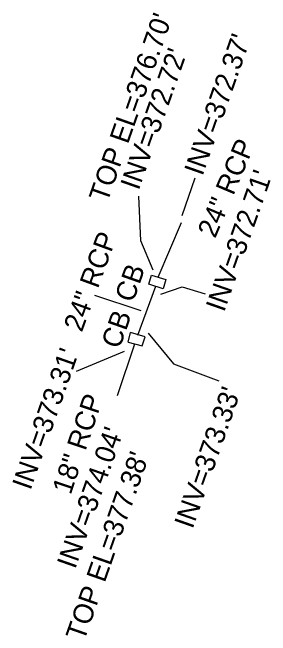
# Model space of a CAD drawing. Extents: x 1975859 to 1978323, y 778892 to 782836.
# Drawn here: x 1977542 to 1977593.8, y 781267.8 to 781393 of the extents above; entities that cross this region are included whole.
import ezdxf

# ---------------------------------------------------------------- set-up
doc = ezdxf.new("R2010")
doc.units = 0
for name, color, linetype in [('Exist Structure Minor Catch Basin', 7, 'Continuous'), ('Exist Structure Minor Catch Basin Text', 7, 'Continuous'), ('Exist Structure Minor Catch Basin Top Elevation', 7, 'Continuous'), ('Exist Structure Minor Pipes RCP 18 Inch', 7, 'Continuous'), ('Exist Structure Minor Pipes RCP 18 Inch Invert', 7, 'Continuous'), ('Exist Structure Minor Pipes RCP 18 Inch Leader', 7, 'Continuous'), ('Exist Structure Minor Pipes RCP 18 Inch Text', 7, 'Continuous'), ('Exist Structure Minor Pipes RCP 24 Inch', 7, 'Continuous'), ('Exist Structure Minor Pipes RCP 24 Inch Invert', 7, 'Continuous'), ('Exist Structure Minor Pipes RCP 24 Inch Leader', 7, 'Continuous'), ('Exist Structure Minor Pipes RCP 24 Inch Text', 7, 'Continuous')]:
    doc.layers.add(name, color=color, linetype=linetype)

msp = doc.modelspace()

# ---------------------------------------------------------------- linework, layer by layer
at = {"layer": 'Exist Structure Minor Catch Basin'}
for p, q in [((1977569.36, 781338.36), (1977569.9, 781340.21)), ((1977565.21, 781326.75), (1977565.7, 781328.65))]:
    msp.add_line(p, q, dxfattribs=at)
for points in [[(1977569.9, 781340.21), (1977572.81, 781339.3), (1977572.23, 781337.46), (1977569.36, 781338.36)], [(1977565.21, 781326.75), (1977568.04, 781326.01), (1977568.62, 781327.78), (1977565.7, 781328.65)]]:
    msp.add_lwpolyline(points, dxfattribs=at)
at = {"layer": 'Exist Structure Minor Pipes RCP 18 Inch'}
msp.add_line((1977563.05, 781316.02), (1977566.53, 781326.38), dxfattribs=at)
at = {"layer": 'Exist Structure Minor Pipes RCP 18 Inch Leader'}
msp.add_lwpolyline([(1977564.44, 781324.85), (1977554.78, 781320.83)], dxfattribs=at)
at = {"layer": 'Exist Structure Minor Pipes RCP 24 Inch'}
for p, q in [((1977571.27, 781339.77), (1977575.93, 781350.79)), ((1977567.18, 781328.11), (1977570.79, 781337.97))]:
    msp.add_line(p, q, dxfattribs=at)
at = {"layer": 'Exist Structure Minor Pipes RCP 24 Inch Leader'}
for points in [[(1977576.04, 781352.18), (1977578.69, 781359.72)], [(1977570.21, 781341.19), (1977567.78, 781347.06), (1977567.39, 781356.07)], [(1977571.79, 781336.38), (1977576.06, 781337.87), (1977580.71, 781336.43)], [(1977567.85, 781332.99), (1977558.5, 781336.07)], [(1977569.21, 781328.51), (1977574.35, 781322.36), (1977583.46, 781318.96)]]:
    msp.add_lwpolyline(points, dxfattribs=at)

# ---------------------------------------------------------------- texts
at = {"layer": 'Exist Structure Minor Catch Basin Text'}
for p in [(1977566.21, 781334.52), (1977563.49, 781325.21)]:
    msp.add_text('CB', height=4, rotation=70.6265, dxfattribs=at).set_placement(p)
at = {"layer": 'Exist Structure Minor Catch Basin Top Elevation'}
for s, p in [("TOP EL=376.70'", (1977561.02, 781354.59)), ("TOP EL=377.38'", (1977556.36, 781266.5))]:
    msp.add_text(s, height=4, rotation=70.6265, dxfattribs=at).set_placement(p)
at = {"layer": 'Exist Structure Minor Pipes RCP 18 Inch Invert'}
for s, p in [("INV=373.31'", (1977545.59, 781296.83)), ("INV=374.04'", (1977554.58, 781280.99))]:
    msp.add_text(s, height=4, rotation=70.6265, dxfattribs=at).set_placement(p)
at = {"layer": 'Exist Structure Minor Pipes RCP 18 Inch Text'}
msp.add_text('18" RCP', height=4, rotation=71.432, dxfattribs=at).set_placement((1977553.67, 781295.91))
at = {"layer": 'Exist Structure Minor Pipes RCP 24 Inch Invert'}
for s, p in [("INV=372.37'", (1977580.14, 781359.96)), ("INV=372.72'", (1977567.32, 781357.07)), ("INV=372.71'", (1977584.48, 781332.61)), ("INV=373.33'", (1977578.14, 781289.06))]:
    msp.add_text(s, height=4, rotation=70.6265, dxfattribs=at).set_placement(p)
at = {"layer": 'Exist Structure Minor Pipes RCP 24 Inch Text'}
for rotation, p in [(67.0547, (1977582.69, 781347.44)), (69.8641, (1977555.91, 781328.58))]:
    msp.add_text('24" RCP', height=4, rotation=rotation, dxfattribs=at).set_placement(p)

doc.saveas('drawing.dxf')
